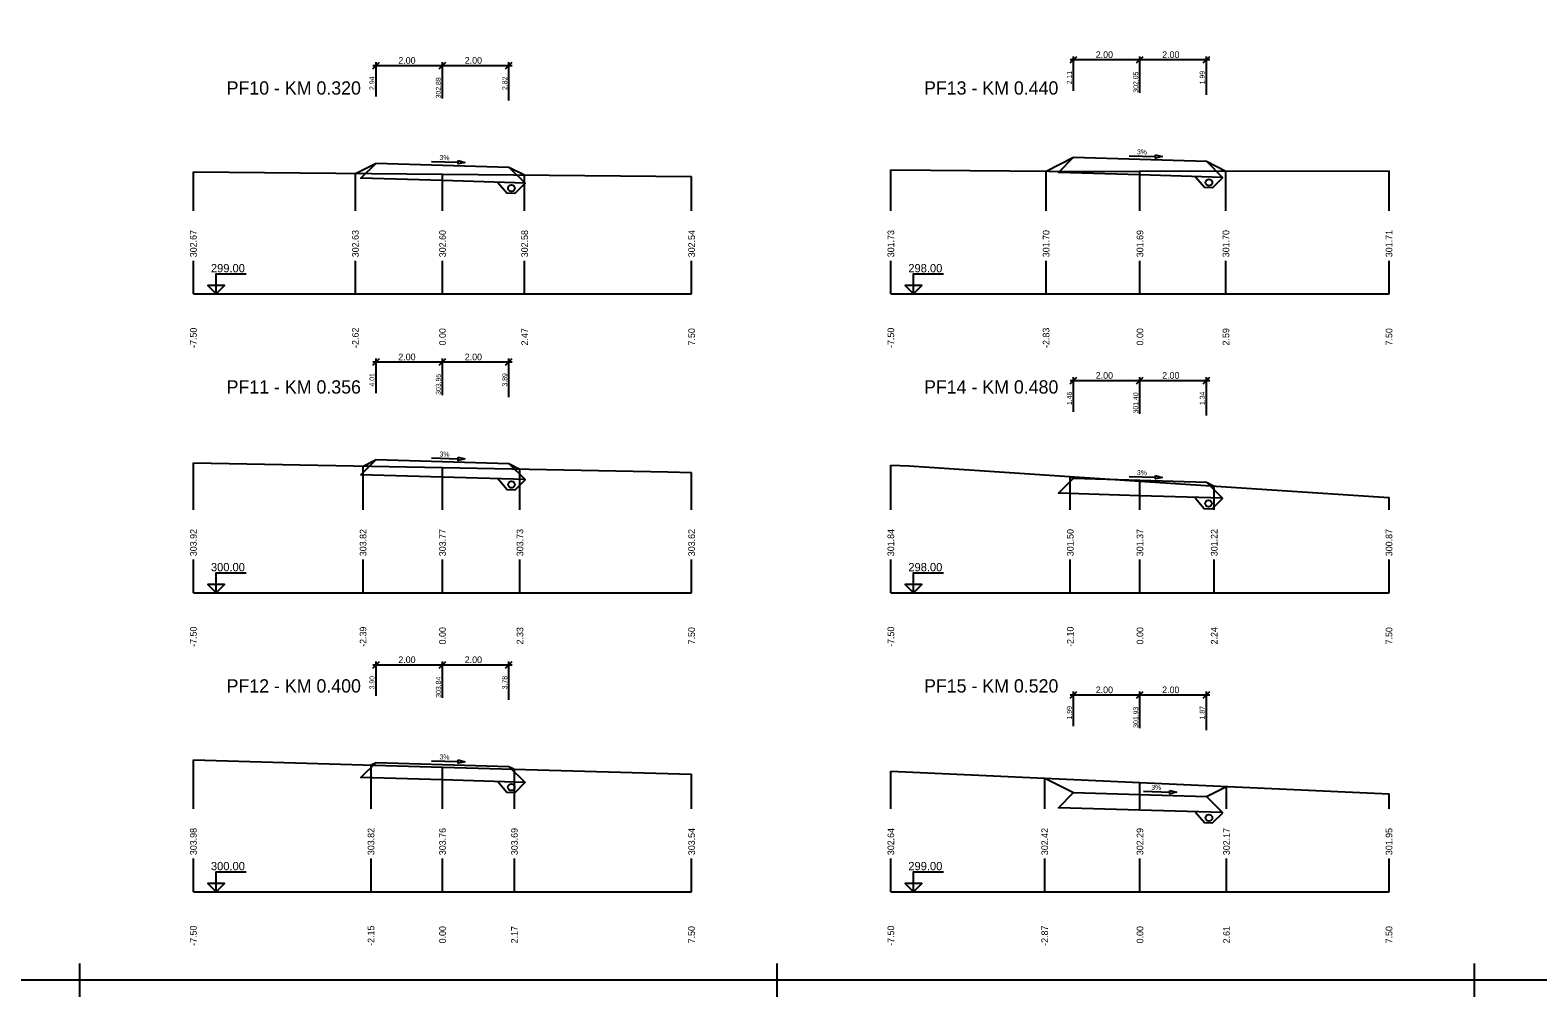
# Model space of a CAD drawing. Extents: x -9 to 2311, y -2 to 597.
# Drawn here: x 610.8 to 1064.8, y -1.6 to 289.4 of the extents above; entities that cross this region are included whole.
import ezdxf

# ---------------------------------------------------------------- set-up
doc = ezdxf.new("R2010")
doc.units = 0
for name, color, linetype in [('KOTA', 7, 'Continuous'), ('KOTA_DELKY', 7, 'Continuous'), ('KOTA_DELKY_CONT', 7, 'Continuous'), ('NS_TELESO_VOZOVKY', 7, 'Continuous'), ('NS_V_PF', 7, 'Continuous'), ('REZY_PF_PUVODNI', 7, 'Continuous'), ('SESTAVY_REZU_PF', 7, 'Continuous'), ('SKLON', 7, 'Continuous'), ('SVK', 7, 'Continuous')]:
    doc.layers.add(name, color=color, linetype=linetype)

msp = doc.modelspace()

# ---------------------------------------------------------------- linework, layer by layer
for p, q in [((625.65, 8.39), (625.65, -1.61)), ((625.65, 8.39), (625.65, -1.61)), ((625.65, 8.39), (625.65, -1.61)), ((625.65, 8.39), (625.65, -1.61)), ((625.65, 8.39), (625.65, -1.61)), ((625.65, 8.39), (625.65, -1.61)), ((625.65, 8.39), (625.65, -1.61)), ((625.65, 8.39), (625.65, -1.61)), ((625.65, 8.39), (625.65, -1.61)), ((625.65, 8.39), (625.65, -1.61)), ((625.65, 8.39), (625.65, -1.61)), ((625.65, 8.39), (625.65, -1.61)), ((835.65, 8.39), (835.65, -1.61)), ((835.65, 8.39), (835.65, -1.61)), ((835.65, 8.39), (835.65, -1.61)), ((835.65, 8.39), (835.65, -1.61)), ((835.65, 8.39), (835.65, -1.61)), ((835.65, 8.39), (835.65, -1.61)), ((835.65, 8.39), (835.65, -1.61)), ((835.65, 8.39), (835.65, -1.61)), ((835.65, 8.39), (835.65, -1.61)), ((835.65, 8.39), (835.65, -1.61)), ((835.65, 8.39), (835.65, -1.61)), ((835.65, 8.39), (835.65, -1.61)), ((1045.65, 8.39), (1045.65, -1.61)), ((1045.65, 8.39), (1045.65, -1.61)), ((1045.65, 8.39), (1045.65, -1.61)), ((1045.65, 8.39), (1045.65, -1.61)), ((1045.65, 8.39), (1045.65, -1.61)), ((1045.65, 8.39), (1045.65, -1.61)), ((1045.65, 8.39), (1045.65, -1.61)), ((1045.65, 8.39), (1045.65, -1.61)), ((1045.65, 8.39), (1045.65, -1.61)), ((1045.65, 8.39), (1045.65, -1.61)), ((1045.65, 8.39), (1045.65, -1.61)), ((1045.65, 8.39), (1045.65, -1.61)), ((630.65, 3.39), (620.65, 3.39)), ((630.65, 3.39), (620.65, 3.39)), ((630.65, 3.39), (620.65, 3.39)), ((630.65, 3.39), (620.65, 3.39)), ((630.65, 3.39), (620.65, 3.39)), ((630.65, 3.39), (620.65, 3.39)), ((630.65, 3.39), (620.65, 3.39)), ((630.65, 3.39), (620.65, 3.39)), ((630.65, 3.39), (620.65, 3.39)), ((630.65, 3.39), (620.65, 3.39)), ((630.65, 3.39), (620.65, 3.39)), ((630.65, 3.39), (620.65, 3.39)), ((840.65, 3.39), (830.65, 3.39)), ((840.65, 3.39), (830.65, 3.39)), ((840.65, 3.39), (830.65, 3.39)), ((840.65, 3.39), (830.65, 3.39)), ((840.65, 3.39), (830.65, 3.39)), ((840.65, 3.39), (830.65, 3.39)), ((840.65, 3.39), (830.65, 3.39)), ((840.65, 3.39), (830.65, 3.39)), ((840.65, 3.39), (830.65, 3.39)), ((840.65, 3.39), (830.65, 3.39)), ((840.65, 3.39), (830.65, 3.39)), ((840.65, 3.39), (830.65, 3.39)), ((1050.65, 3.39), (1040.65, 3.39)), ((1050.65, 3.39), (1040.65, 3.39)), ((1050.65, 3.39), (1040.65, 3.39)), ((1050.65, 3.39), (1040.65, 3.39)), ((1050.65, 3.39), (1040.65, 3.39)), ((1050.65, 3.39), (1040.65, 3.39)), ((1050.65, 3.39), (1040.65, 3.39)), ((1050.65, 3.39), (1040.65, 3.39)), ((1050.65, 3.39), (1040.65, 3.39)), ((1050.65, 3.39), (1040.65, 3.39)), ((1050.65, 3.39), (1040.65, 3.39)), ((1050.65, 3.39), (1040.65, 3.39))]:
    msp.add_line(p, q)
msp.add_lwpolyline([(-4.35, 597.39), (2305.65, 597.39), (2305.65, 3.39), (-4.35, 3.39)], close=True)
for points in [[(759.8, 243.25), (756.74, 240.21), (754.4, 240.31), (751.69, 243.44)], [(969.85, 244.94), (966.8, 241.9), (964.45, 242), (961.75, 245.14)], [(759.86, 153.99), (756.81, 150.95), (754.46, 151.05), (751.75, 154.19)], [(969.71, 148.29), (966.66, 145.25), (964.31, 145.35), (961.6, 148.49)], [(759.78, 62.88), (756.73, 59.84), (754.38, 59.94), (751.67, 63.08)], [(969.83, 53.69), (966.78, 50.65), (964.44, 50.75), (961.73, 53.89)]]:
    msp.add_lwpolyline(points)
for centre in [(755.74, 241.84), (965.79, 243.54), (755.8, 152.59), (965.65, 146.88), (755.72, 61.48), (965.78, 52.29)]:
    msp.add_circle(centre, 1)
at = {"layer": 'KOTA'}
for points in [[(666.85, 212.5), (664.35, 212.5), (666.85, 210), (666.85, 216), (675.85, 216)], [(876.85, 212.5), (874.35, 212.5), (876.85, 210), (876.85, 216), (885.85, 216)], [(666.85, 210), (669.35, 212.5), (666.85, 212.5)], [(876.85, 210), (879.35, 212.5), (876.85, 212.5)], [(666.85, 122.5), (664.35, 122.5), (666.85, 120), (666.85, 126), (675.85, 126)], [(876.85, 122.5), (874.35, 122.5), (876.85, 120), (876.85, 126), (885.85, 126)], [(666.85, 120), (669.35, 122.5), (666.85, 122.5)], [(876.85, 120), (879.35, 122.5), (876.85, 122.5)], [(666.85, 32.5), (664.35, 32.5), (666.85, 30), (666.85, 36), (675.85, 36)], [(666.85, 30), (669.35, 32.5), (666.85, 32.5)], [(876.85, 32.5), (874.35, 32.5), (876.85, 30), (876.85, 36), (885.85, 36)], [(876.85, 30), (879.35, 32.5), (876.85, 32.5)]]:
    msp.add_lwpolyline(points, dxfattribs=at)
at = {"layer": 'KOTA_DELKY'}
for points in [[(924, 279.52), (926, 281.52)], [(925, 271.12), (925, 281.52)], [(944, 279.52), (946, 281.52)], [(944, 279.52), (946, 281.52)], [(945, 270.52), (945, 281.52)], [(945, 270.52), (945, 281.52)], [(964, 279.52), (966, 281.52)], [(965, 269.92), (965, 281.52)], [(714, 277.8), (716, 279.8)], [(714, 278.8), (736, 278.8)], [(715, 269.4), (715, 279.8)], [(734, 277.8), (736, 279.8)], [(734, 277.8), (736, 279.8)], [(734, 278.8), (756, 278.8)], [(735, 268.8), (735, 279.8)], [(735, 268.8), (735, 279.8)], [(754, 277.8), (756, 279.8)], [(755, 268.2), (755, 279.8)], [(924, 280.52), (946, 280.52)], [(944, 280.52), (966, 280.52)], [(714, 188.53), (716, 190.53)], [(714, 189.53), (736, 189.53)], [(715, 180.13), (715, 190.53)], [(734, 188.53), (736, 190.53)], [(734, 188.53), (736, 190.53)], [(734, 189.53), (756, 189.53)], [(735, 179.53), (735, 190.53)], [(735, 179.53), (735, 190.53)], [(754, 188.53), (756, 190.53)], [(755, 178.93), (755, 190.53)], [(924, 182.95), (926, 184.95)], [(924, 183.95), (946, 183.95)], [(925, 174.55), (925, 184.95)], [(944, 182.95), (946, 184.95)], [(944, 182.95), (946, 184.95)], [(944, 183.95), (966, 183.95)], [(945, 173.95), (945, 184.95)], [(945, 173.95), (945, 184.95)], [(964, 182.95), (966, 184.95)], [(965, 173.35), (965, 184.95)], [(714, 97.37), (716, 99.37)], [(714, 98.37), (736, 98.37)], [(715, 88.97), (715, 99.37)], [(734, 97.37), (736, 99.37)], [(734, 97.37), (736, 99.37)], [(734, 98.37), (756, 98.37)], [(735, 88.37), (735, 99.37)], [(735, 88.37), (735, 99.37)], [(754, 97.37), (756, 99.37)], [(755, 87.77), (755, 99.37)], [(924, 88.31), (926, 90.31)], [(924, 89.31), (946, 89.31)], [(925, 79.91), (925, 90.31)], [(944, 88.31), (946, 90.31)], [(944, 88.31), (946, 90.31)], [(944, 89.31), (966, 89.31)], [(945, 79.31), (945, 90.31)], [(945, 79.31), (945, 90.31)], [(964, 88.31), (966, 90.31)], [(965, 78.71), (965, 90.31)]]:
    msp.add_lwpolyline(points, dxfattribs=at)
at = {"layer": 'NS_TELESO_VOZOVKY'}
for points in [[(945, 250.52), (965, 249.92), (965, 249.92), (969.85, 245.07), (945, 245.82), (920.44, 246.55), (925, 251.12), (925, 251.12), (945, 250.52)], [(735, 248.8), (755, 248.2), (755, 248.2), (759.85, 243.35), (735, 244.1), (710.44, 244.83), (715, 249.4), (715, 249.4), (735, 248.8)], [(735, 159.53), (755, 158.93), (755, 158.93), (759.85, 154.09), (735, 154.83), (710.44, 155.57), (715, 160.13), (715, 160.13), (735, 159.53)], [(945, 153.95), (965, 153.35), (965, 153.35), (969.85, 148.51), (945, 149.25), (920.44, 149.99), (925, 154.55), (925, 154.55), (945, 153.95)], [(735, 68.37), (755, 67.77), (755, 67.77), (759.85, 62.92), (735, 63.67), (710.44, 64.4), (715, 68.97), (715, 68.97), (735, 68.37)], [(945, 59.31), (965, 58.71), (965, 58.71), (969.85, 53.86), (945, 54.61), (920.44, 55.34), (925, 59.91), (925, 59.91), (945, 59.31)]]:
    msp.add_lwpolyline(points, dxfattribs=at)
at = {"layer": 'NS_V_PF'}
for points in [[(916.75, 246.99), (925, 251.12), (925, 251.12), (945, 250.52), (965, 249.92), (965, 249.92), (970.89, 246.97)], [(708.77, 246.28), (715, 249.4), (715, 249.4), (735, 248.8), (755, 248.2), (755, 248.2), (759.73, 245.83)], [(711.09, 158.18), (715, 160.13), (715, 160.13), (735, 159.53), (755, 158.93), (755, 158.93), (758.32, 157.28)], [(924.02, 155.04), (925, 154.55), (925, 154.55), (945, 153.95), (965, 153.35), (965, 153.35), (967.36, 152.17)], [(713.47, 68.2), (715, 68.97), (715, 68.97), (735, 68.37), (755, 67.77), (755, 67.77), (756.66, 66.94)], [(916.32, 64.25), (925, 59.91), (925, 59.91), (945, 59.31), (965, 58.71), (965, 58.71), (971.06, 61.74)]]:
    msp.add_lwpolyline(points, dxfattribs=at)
at = {"layer": 'REZY_PF_PUVODNI'}
for points in [[(660, 246.71), (735, 246.05), (735, 246.05), (810, 245.39)], [(870, 247.33), (929.53, 246.89), (945, 246.92), (945, 246.92), (1020, 247.07)], [(660, 159.16), (735, 157.72), (735, 157.72), (802.88, 156.42), (810, 156.24)], [(870, 158.41), (875.5, 158.25), (945, 153.65), (945, 153.65), (1019.99, 148.69), (1020, 148.69)], [(660, 69.77), (735, 67.57), (735, 67.57), (810, 65.38)], [(870, 66.37), (945, 62.93), (945, 62.93), (1020, 59.49)]]:
    msp.add_lwpolyline(points, dxfattribs=at)
at = {"layer": 'SESTAVY_REZU_PF'}
for points in [[(660, 210), (810, 210)], [(870, 210), (1020, 210)], [(660, 120), (810, 120)], [(870, 120), (1020, 120)], [(660, 30), (810, 30)], [(870, 30), (1020, 30)]]:
    msp.add_lwpolyline(points, dxfattribs=at)
at = {"layer": 'SKLON'}
for points in [[(731.71, 249.89), (739.71, 249.65)], [(739.73, 250.15), (741.71, 249.59), (739.7, 249.15), (739.73, 250.15)], [(941.71, 251.61), (949.71, 251.37)], [(949.73, 251.87), (951.71, 251.32), (949.7, 250.88), (949.73, 251.87)], [(731.71, 160.63), (739.71, 160.39)], [(739.73, 160.89), (741.71, 160.33), (739.7, 159.89), (739.73, 160.89)], [(941.71, 155.05), (949.71, 154.81)], [(949.73, 155.31), (951.71, 154.75), (949.7, 154.31), (949.73, 155.31)], [(731.71, 69.47), (739.71, 69.23)], [(739.73, 69.73), (741.71, 69.17), (739.7, 68.73), (739.73, 69.73)], [(946.03, 60.28), (954.02, 60.04)], [(954.04, 60.54), (956.02, 59.98), (954.01, 59.54), (954.04, 60.54)]]:
    msp.add_lwpolyline(points, dxfattribs=at)
at = {"layer": 'SVK'}
for points in [[(660, 235), (660, 246.71)], [(708.77, 235), (708.77, 246.28)], [(735, 235), (735, 246.05)], [(759.73, 235), (759.73, 245.83)], [(810, 235), (810, 245.39)], [(870, 235), (870, 247.33)], [(916.75, 235), (916.75, 246.99)], [(945, 235), (945, 246.92)], [(970.89, 235), (970.89, 246.97)], [(1020, 235), (1020, 247.07)], [(660, 210), (660, 220)], [(708.77, 210), (708.77, 220)], [(735, 210), (735, 220)], [(759.73, 210), (759.73, 220)], [(810, 210), (810, 220)], [(870, 210), (870, 220)], [(916.75, 210), (916.75, 220)], [(945, 210), (945, 220)], [(970.89, 210), (970.89, 220)], [(1020, 210), (1020, 220)], [(660, 145), (660, 159.16)], [(711.09, 145), (711.09, 158.18)], [(735, 145), (735, 157.72)], [(758.32, 145), (758.32, 157.28)], [(810, 145), (810, 156.24)], [(870, 145), (870, 158.41)], [(924.02, 145), (924.02, 155.04)], [(945, 145), (945, 153.65)], [(967.36, 145), (967.36, 152.17)], [(1020, 145), (1020, 148.69)], [(660, 120), (660, 130)], [(711.09, 120), (711.09, 130)], [(735, 120), (735, 130)], [(758.32, 120), (758.32, 130)], [(810, 120), (810, 130)], [(870, 120), (870, 130)], [(924.02, 120), (924.02, 130)], [(945, 120), (945, 130)], [(967.36, 120), (967.36, 130)], [(1020, 120), (1020, 130)], [(660, 55), (660, 69.77)], [(713.47, 55), (713.47, 68.2)], [(735, 55), (735, 67.57)], [(756.66, 55), (756.66, 66.94)], [(810, 55), (810, 65.38)], [(870, 55), (870, 66.37)], [(916.32, 55), (916.32, 64.25)], [(945, 55), (945, 62.93)], [(971.06, 55), (971.06, 61.74)], [(1020, 55), (1020, 59.49)], [(660, 30), (660, 40)], [(713.47, 30), (713.47, 40)], [(735, 30), (735, 40)], [(756.66, 30), (756.66, 40)], [(810, 30), (810, 40)], [(870, 30), (870, 40)], [(916.32, 30), (916.32, 40)], [(945, 30), (945, 40)], [(971.06, 30), (971.06, 40)], [(1020, 30), (1020, 40)]]:
    msp.add_lwpolyline(points, dxfattribs=at)

# ---------------------------------------------------------------- texts
at = {"layer": 'KOTA'}
for s, p in [('299.00', (665.27, 216.5)), ('298.00', (875.27, 216.5)), ('300.00', (665.27, 126.5)), ('298.00', (875.27, 126.5)), ('300.00', (665.27, 36.5)), ('299.00', (875.27, 36.5))]:
    msp.add_text(s, height=2.5, dxfattribs=at).set_placement(p)
at = {"layer": 'KOTA_DELKY'}
for p in [(931.69, 281.02), (951.69, 281.02), (721.69, 279.3), (741.69, 279.3), (721.69, 190.03), (741.69, 190.03), (931.69, 184.45), (951.69, 184.45), (721.69, 98.87), (741.69, 98.87), (931.69, 89.81), (951.69, 89.81)]:
    msp.add_text('2.00', height=2, dxfattribs=at).set_placement(p)
at = {"layer": 'KOTA_DELKY_CONT'}
for s, p in [('2.94', (714.5, 271.39)), ('302.88', (734.5, 268.87)), ('2.82', (754.5, 271.39)), ('2.11', (924.5, 273.11)), ('302.05', (944.5, 270.59)), ('1.99', (964.5, 273.11)), ('4.01', (714.5, 182.12)), ('303.95', (734.5, 179.61)), ('3.89', (754.5, 182.12)), ('1.46', (924.5, 176.54)), ('301.40', (944.5, 174.03)), ('1.34', (964.5, 176.54)), ('3.90', (714.5, 90.96)), ('303.84', (734.5, 88.44)), ('3.78', (754.5, 90.96)), ('1.99', (924.5, 81.9)), ('301.93', (944.5, 79.38)), ('1.87', (964.5, 81.9))]:
    msp.add_text(s, height=1.5, rotation=90, dxfattribs=at).set_placement(p)
at = {"layer": 'SESTAVY_REZU_PF'}
for s, p in [('PF10 - KM 0.320', (670, 270)), ('PF13 - KM 0.440', (880, 270)), ('PF11 - KM 0.356', (670, 180)), ('PF14 - KM 0.480', (880, 180)), ('PF12 - KM 0.400', (670, 90)), ('PF15 - KM 0.520', (880, 90))]:
    msp.add_text(s, height=4, dxfattribs=at).set_placement(p)
at = {"layer": 'SKLON'}
for p in [(734.09, 250.32), (944.09, 252.04), (734.09, 161.06), (944.09, 155.48), (734.09, 69.9), (948.4, 60.7)]:
    msp.add_text('3%', height=1.5, rotation=358.2816, dxfattribs=at).set_placement(p)
at = {"layer": 'SVK'}
for s, p in [(' 302.67', (661, 220.3)), (' 302.63', (709.77, 220.3)), (' 302.60', (736, 220.3)), (' 302.58', (760.73, 220.3)), (' 302.54', (811, 220.3)), (' 301.73', (871, 220.3)), (' 301.70', (917.75, 220.3)), (' 301.69', (946, 220.3)), (' 301.70', (971.89, 220.3)), (' 301.71', (1021, 220.3)), (' -7.50', (661, 193)), (' -2.62', (709.77, 193)), ('  0.00', (736, 193)), ('  2.47', (760.73, 193)), ('  7.50', (811, 193)), (' -7.50', (871, 193)), (' -2.83', (917.75, 193)), ('  0.00', (946, 193)), ('  2.59', (971.89, 193)), ('  7.50', (1021, 193)), (' 303.92', (661, 130.3)), (' 303.82', (712.09, 130.3)), (' 303.77', (736, 130.3)), (' 303.73', (759.32, 130.3)), (' 303.62', (811, 130.3)), (' 301.84', (871, 130.3)), (' 301.50', (925.02, 130.3)), (' 301.37', (946, 130.3)), (' 301.22', (968.36, 130.3)), (' 300.87', (1021, 130.3)), (' -7.50', (661, 103)), (' -2.39', (712.09, 103)), ('  0.00', (736, 103)), ('  2.33', (759.32, 103)), ('  7.50', (811, 103)), (' -7.50', (871, 103)), (' -2.10', (925.02, 103)), ('  0.00', (946, 103)), ('  2.24', (968.36, 103)), ('  7.50', (1021, 103)), (' 303.98', (661, 40.3)), (' 303.82', (714.47, 40.3)), (' 303.76', (736, 40.3)), (' 303.69', (757.66, 40.3)), (' 303.54', (811, 40.3)), (' 302.64', (871, 40.3)), (' 302.42', (917.32, 40.3)), (' 302.29', (946, 40.3)), (' 302.17', (972.06, 40.3)), (' 301.95', (1021, 40.3)), (' -7.50', (661, 13)), (' -2.15', (714.47, 13)), ('  0.00', (736, 13)), ('  2.17', (757.66, 13)), ('  7.50', (811, 13)), (' -7.50', (871, 13)), (' -2.87', (917.32, 13)), ('  0.00', (946, 13)), ('  2.61', (972.06, 13)), ('  7.50', (1021, 13))]:
    msp.add_text(s, height=2, rotation=90, dxfattribs=at).set_placement(p)

doc.saveas('drawing.dxf')
